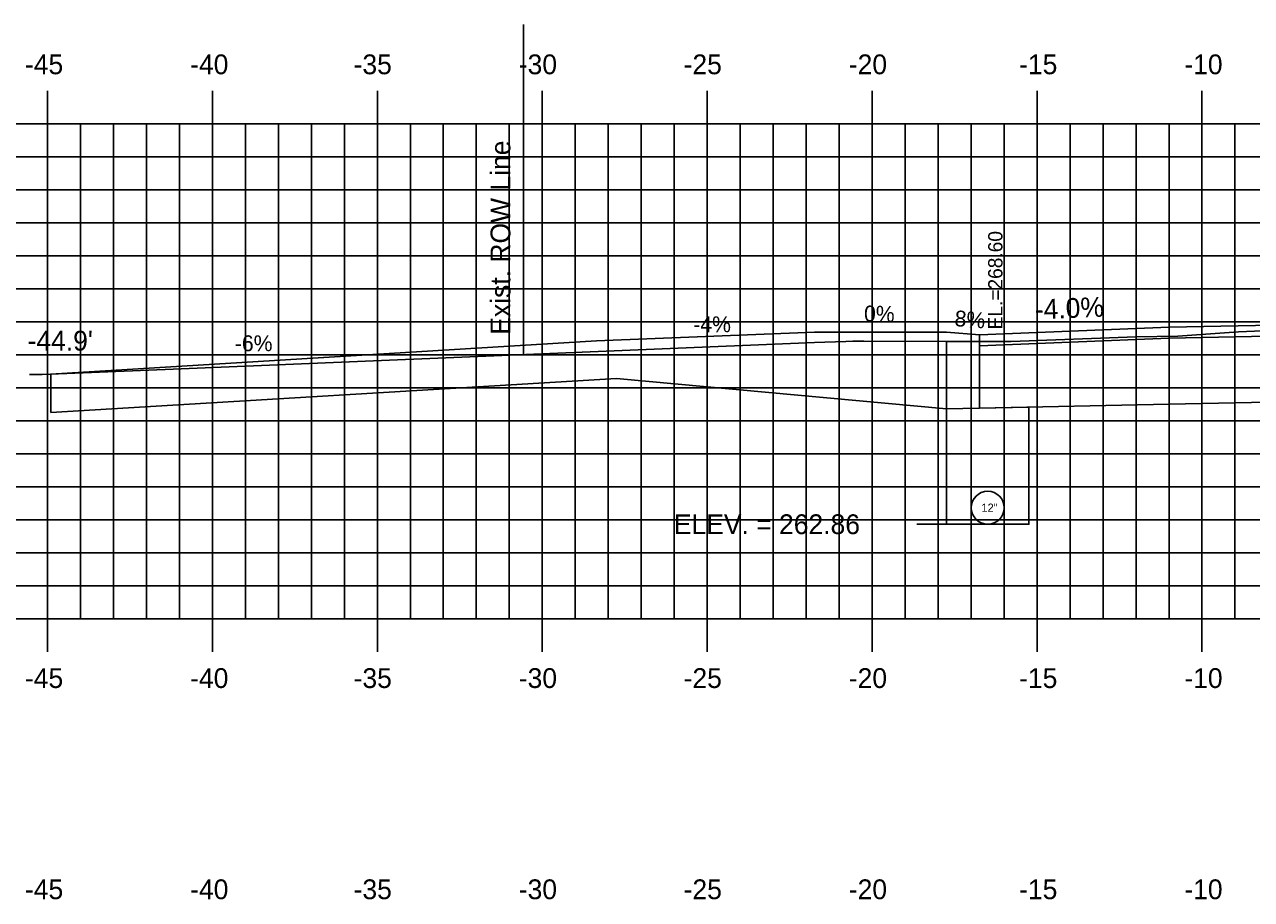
# Model space of a CAD drawing. Extents: x 855344 to 855514, y 366268 to 366378.
# Drawn here: x 855381.41 to 855418.61, y 366298.73 to 366325.24 of the extents above; entities that cross this region are included whole.
import ezdxf

# ---------------------------------------------------------------- set-up
doc = ezdxf.new("R2010")
doc.units = 0
for name, color, linetype in [('ANNOTATION', 7, 'Continuous'), ('D_Roadway_Drive_Gravel_LT', 7, 'Continuous'), ('D_Roadway_Drive_SubGrade', 7, 'Continuous'), ('D_Roadway_Edge_Shoulder', 7, 'Continuous'), ('D_Roadway_SubGrade', 7, 'Continuous'), ('D_Text_Standard', 7, 'Continuous'), ('E_ROW_Line', 7, 'Continuous'), ('H_V ANNOTATION', 7, 'Continuous'), ('JUNK COM EXC', 7, 'Continuous'), ('junk strct exc', 7, 'Continuous'), ('MAJOR', 7, 'Continuous'), ('MINOR', 7, 'Continuous'), ('PDRAIN', 7, 'Continuous'), ('S_Roadway_Centerline', 7, 'Continuous')]:
    doc.layers.add(name, color=color, linetype=linetype)

msp = doc.modelspace()

# ---------------------------------------------------------------- linework, layer by layer
at = {"layer": 'D_Roadway_Drive_Gravel_LT'}
for p, q in [((855405.364, 366315.919), (855398.755, 366315.654)), ((855409.364, 366315.919), (855405.364, 366315.919)), ((855410.364, 366315.839), (855409.364, 366315.919)), ((855410.364, 366315.506), (855410.364, 366315.839)), ((855398.755, 366315.654), (855382.21, 366314.651)), ((855399.364, 366314.514), (855382.21, 366313.485))]:
    msp.add_line(p, q, dxfattribs=at)
at = {"layer": 'D_Roadway_Drive_SubGrade'}
for p, q in [((855382.21, 366314.651), (855382.21, 366313.485)), ((855409.364, 366313.6), (855399.364, 366314.514)), ((855410.364, 366313.62), (855409.364, 366313.6))]:
    msp.add_line(p, q, dxfattribs=at)
at = {"layer": 'D_Roadway_Edge_Shoulder'}
msp.add_lwpolyline([(855410.364, 366315.839), (855416.11, 366316.069), (855427.11, 366316.288), (855438.11, 366316.068), (855442.107, 366315.908)], dxfattribs=at)
at = {"layer": 'D_Roadway_SubGrade'}
for points in [[(855416.11, 366315.735), (855410.364, 366315.506), (855410.364, 366313.62), (855416.11, 366313.735)], [(855416.11, 366313.735), (855416.11, 366315.735), (855427.11, 366315.955), (855438.11, 366315.735), (855438.11, 366313.735), (855427.11, 366313.955)]]:
    msp.add_lwpolyline(points, close=True, dxfattribs=at)
at = {"layer": 'D_Text_Standard'}
msp.add_lwpolyline([(855409.364, 366310.099), (855409.148, 366310.099), (855408.468, 366310.099)], dxfattribs=at)
at = {"layer": 'E_ROW_Line'}
msp.add_line((855396.542, 366315.242), (855396.542, 366325.242), dxfattribs=at)
at = {"layer": 'JUNK COM EXC'}
msp.add_lwpolyline([(855442.11, 366313.656), (855443.109, 366313.636), (855447.908, 366313.54), (855455.458, 366314.866), (855455.458, 366316.033), (855450.115, 366316.007), (855445.453, 366315.764), (855445.301, 366315.765), (855442.641, 366316.173), (855438.522, 366316.091), (855438.043, 366316.107), (855433.603, 366316.181), (855427.262, 366316.303), (855418.219, 366315.925), (855416.377, 366315.798), (855415.114, 366315.783), (855411.326, 366315.64), (855409.364, 366315.641), (855409.364, 366313.6), (855410.364, 366313.62), (855416.11, 366313.735), (855427.11, 366313.955), (855438.11, 366313.735), (855440.11, 366313.695)], close=True, dxfattribs=at)
at = {"layer": 'junk strct exc'}
msp.add_lwpolyline([(855409.364, 366313.6), (855409.364, 366310.099), (855411.864, 366310.099), (855411.864, 366313.65)], close=True, dxfattribs=at)
at = {"layer": 'MAJOR'}
for p, q in [((855382.11, 366323.238), (855382.11, 366322.236)), ((855387.11, 366323.238), (855387.11, 366322.236)), ((855392.11, 366323.238), (855392.11, 366322.236)), ((855397.11, 366323.238), (855397.11, 366322.236)), ((855402.11, 366323.238), (855402.11, 366322.236)), ((855407.11, 366323.238), (855407.11, 366322.236)), ((855412.11, 366323.238), (855412.11, 366322.236)), ((855417.11, 366323.238), (855417.11, 366322.236)), ((855357.11, 366322.236), (855497.11, 366322.236)), ((855357.11, 366322.236), (855497.11, 366322.236)), ((855382.11, 366307.236), (855382.11, 366322.236)), ((855387.11, 366307.236), (855387.11, 366322.236)), ((855392.11, 366307.236), (855392.11, 366322.236)), ((855397.11, 366307.236), (855397.11, 366322.236)), ((855402.11, 366307.236), (855402.11, 366322.236)), ((855407.11, 366307.236), (855407.11, 366322.236)), ((855412.11, 366307.236), (855412.11, 366322.236)), ((855417.11, 366307.236), (855417.11, 366322.236)), ((855357.11, 366317.236), (855497.11, 366317.236)), ((855357.11, 366312.236), (855497.11, 366312.236)), ((855357.11, 366307.236), (855497.11, 366307.236)), ((855357.11, 366307.236), (855497.11, 366307.236)), ((855382.11, 366306.234), (855382.11, 366307.236)), ((855387.11, 366306.234), (855387.11, 366307.236)), ((855392.11, 366306.234), (855392.11, 366307.236)), ((855397.11, 366306.234), (855397.11, 366307.236)), ((855402.11, 366306.234), (855402.11, 366307.236)), ((855407.11, 366306.234), (855407.11, 366307.236)), ((855412.11, 366306.234), (855412.11, 366307.236)), ((855417.11, 366306.234), (855417.11, 366307.236))]:
    msp.add_line(p, q, dxfattribs=at)
at = {"layer": 'MINOR'}
for p, q in [((855383.11, 366307.236), (855383.11, 366322.236)), ((855384.11, 366307.236), (855384.11, 366322.236)), ((855385.11, 366307.236), (855385.11, 366322.236)), ((855386.11, 366307.236), (855386.11, 366322.236)), ((855388.11, 366307.236), (855388.11, 366322.236)), ((855389.11, 366307.236), (855389.11, 366322.236)), ((855390.11, 366307.236), (855390.11, 366322.236)), ((855391.11, 366307.236), (855391.11, 366322.236)), ((855393.11, 366307.236), (855393.11, 366322.236)), ((855394.11, 366307.236), (855394.11, 366322.236)), ((855395.11, 366307.236), (855395.11, 366322.236)), ((855396.11, 366307.236), (855396.11, 366322.236)), ((855398.11, 366307.236), (855398.11, 366322.236)), ((855399.11, 366307.236), (855399.11, 366322.236)), ((855400.11, 366307.236), (855400.11, 366322.236)), ((855401.11, 366307.236), (855401.11, 366322.236)), ((855403.11, 366307.236), (855403.11, 366322.236)), ((855404.11, 366307.236), (855404.11, 366322.236)), ((855405.11, 366307.236), (855405.11, 366322.236)), ((855406.11, 366307.236), (855406.11, 366322.236)), ((855408.11, 366307.236), (855408.11, 366322.236)), ((855409.11, 366307.236), (855409.11, 366322.236)), ((855410.11, 366307.236), (855410.11, 366322.236)), ((855411.11, 366307.236), (855411.11, 366322.236)), ((855413.11, 366307.236), (855413.11, 366322.236)), ((855414.11, 366307.236), (855414.11, 366322.236)), ((855415.11, 366307.236), (855415.11, 366322.236)), ((855416.11, 366307.236), (855416.11, 366322.236)), ((855418.11, 366307.236), (855418.11, 366322.236)), ((855357.11, 366321.236), (855497.11, 366321.236)), ((855357.11, 366320.236), (855497.11, 366320.236)), ((855357.11, 366319.236), (855497.11, 366319.236)), ((855357.11, 366318.236), (855497.11, 366318.236)), ((855357.11, 366316.236), (855497.11, 366316.236)), ((855357.11, 366315.236), (855497.11, 366315.236)), ((855357.11, 366314.236), (855497.11, 366314.236)), ((855357.11, 366313.236), (855497.11, 366313.236)), ((855357.11, 366311.236), (855497.11, 366311.236)), ((855357.11, 366310.236), (855497.11, 366310.236)), ((855357.11, 366309.236), (855497.11, 366309.236)), ((855357.11, 366308.236), (855497.11, 366308.236))]:
    msp.add_line(p, q, dxfattribs=at)
at = {"layer": 'PDRAIN'}
msp.add_lwpolyline([(855409.364, 366313.6), (855409.364, 366310.099), (855411.864, 366310.099), (855411.864, 366313.6)], dxfattribs=at)
msp.add_circle((855410.614, 366310.599), 0.5, dxfattribs=at)
at = {"layer": 'S_Roadway_Centerline'}
msp.add_lwpolyline([(855381.561, 366314.634), (855381.949, 366314.641), (855385.679, 366314.793), (855405.358, 366315.606), (855406.311, 366315.638), (855406.526, 366315.649), (855406.86, 366315.642), (855411.326, 366315.64), (855415.114, 366315.783), (855416.377, 366315.798), (855418.219, 366315.925), (855427.262, 366316.303), (855433.603, 366316.181), (855438.043, 366316.107), (855438.522, 366316.091), (855442.641, 366316.173), (855445.301, 366315.765), (855445.453, 366315.764), (855450.115, 366316.007), (855461.901, 366316.064), (855468.238, 366316.148), (855471.911, 366316.218), (855474.551, 366316.376)], dxfattribs=at)

# ---------------------------------------------------------------- texts
at = {"layer": 'ANNOTATION'}
msp.add_text('-4.0%', height=0.6, rotation=2.2906, dxfattribs=at).set_placement((855412.053, 366316.307))
at = {"layer": 'D_Roadway_Drive_Gravel_LT'}
for s, rotation, p in [('0%', 358.8078, (855406.86, 366316.247)), ('8%', 355.4261, (855409.595, 366316.106))]:
    msp.add_text(s, height=0.48, rotation=rotation, dxfattribs=at).set_placement(p)
for s, p in [(' -4%', (855401.51, 366315.919)), (' -6%', (855387.612, 366315.343))]:
    msp.add_text(s, height=0.48, dxfattribs=at).set_placement(p)
at = {"layer": 'D_Text_Standard'}
msp.add_text(' EL.=268.60', height=0.4335, rotation=90, dxfattribs=at).set_placement((855411.061, 366315.842))
for s, p in [("-44.9'", (855381.505, 366315.361)), ('ELEV. = 262.86', (855401.099, 366309.799))]:
    msp.add_text(s, height=0.6, dxfattribs=at).set_placement(p)
at = {"layer": 'E_ROW_Line'}
msp.add_text('Exist. ROW Line', height=0.6, rotation=90, dxfattribs=at).set_placement((855396.142, 366315.842))
at = {"layer": 'H_V ANNOTATION'}
for s, p in [('-45', (855381.427, 366323.736)), ('-40', (855386.435, 366323.736)), ('-35', (855391.39, 366323.736)), ('-30', (855396.398, 366323.736)), ('-25', (855401.395, 366323.736)), ('-20', (855406.403, 366323.736)), ('-15', (855411.566, 366323.736)), ('-10', (855416.575, 366323.736)), ('-45', (855381.427, 366305.136)), ('-40', (855386.435, 366305.136)), ('-35', (855391.39, 366305.136)), ('-30', (855396.398, 366305.136)), ('-25', (855401.395, 366305.136)), ('-20', (855406.403, 366305.136)), ('-15', (855411.566, 366305.136)), ('-10', (855416.575, 366305.136)), ('-45', (855381.427, 366298.736)), ('-40', (855386.435, 366298.736)), ('-35', (855391.39, 366298.736)), ('-30', (855396.398, 366298.736)), ('-25', (855401.395, 366298.736)), ('-20', (855406.403, 366298.736)), ('-15', (855411.566, 366298.736)), ('-10', (855416.575, 366298.736))]:
    msp.add_text(s, height=0.6, dxfattribs=at).set_placement(p)
at = {"layer": 'PDRAIN'}
msp.add_text('12"', height=0.25, dxfattribs=at).set_placement((855410.423, 366310.475))

doc.saveas('drawing.dxf')
